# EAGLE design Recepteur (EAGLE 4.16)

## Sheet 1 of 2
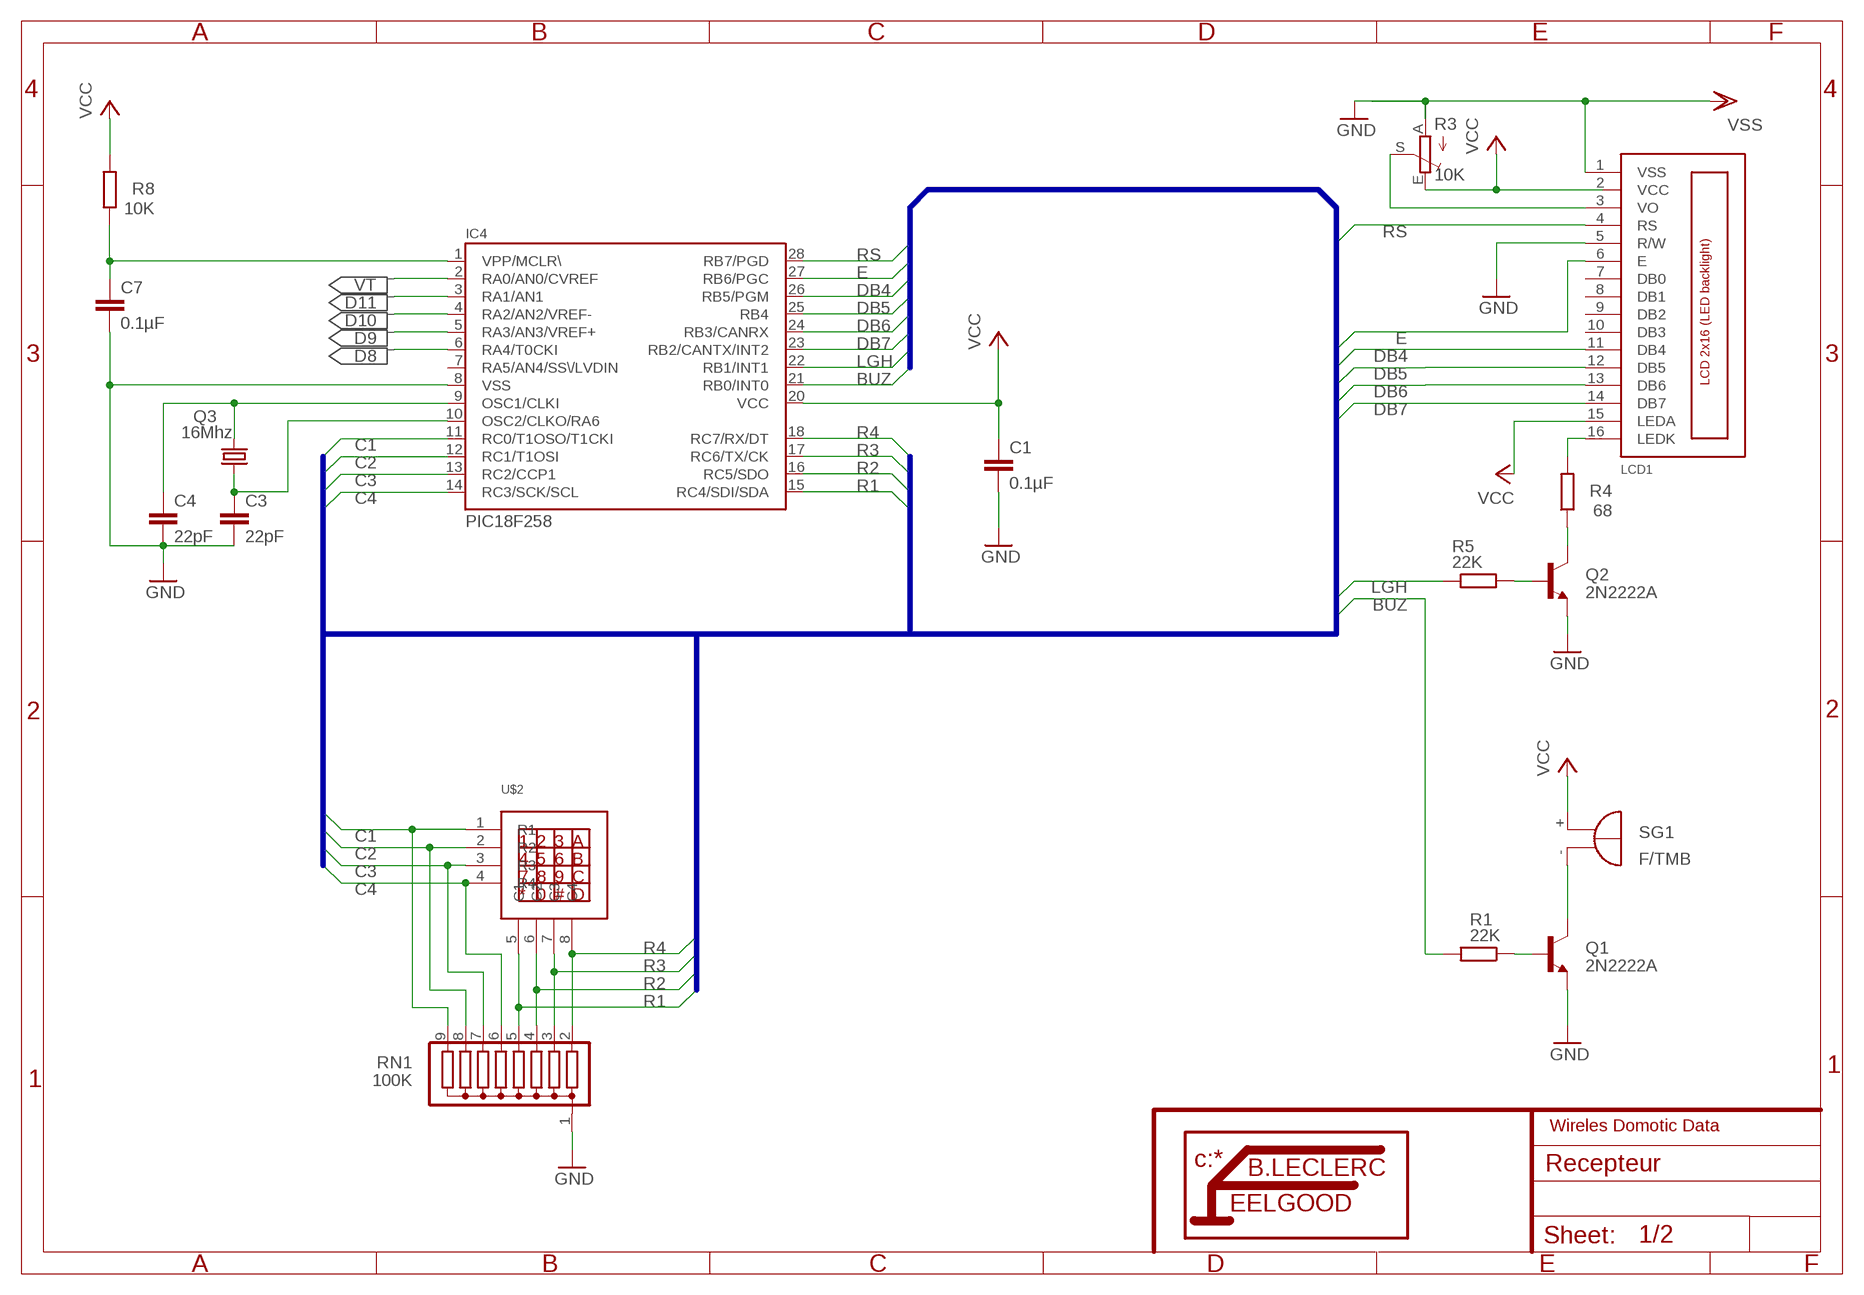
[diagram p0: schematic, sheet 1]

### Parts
C1  0.1µF  C-EU102-043X133  [C102-043X133]
C3  22pF  C-EU025-030X050  [C025-030X050]
C4  22pF  C-EU025-030X050  [C025-030X050]
C7  0.1µF  C-EU102-043X133  [C102-043X133]
IC4  PIC18F258  [DIL28]
LCD1  LCD_2X16_SIL  [HY-1602F]
Q1  2N2222A  [TO18]
Q2  2N2222A  [TO18]
Q3  16Mhz  CRYTALHC49U70  [HC49U70]
R1  22K  R-EU_0207/10  [0207/10]
R3  10K  TRIM_EU-LI10  [LI10]
R4  68  R-EU_0207/10  [0207/10]
R5  22K  R-EU_0207/10  [0207/10]
R8  10K  R-EU_0207/10  [0207/10]
RN1  100K  G08R  [SIL9]
SG1  F/TMB  [F/TMB]
U$2  KEYPAD4X4  [KEYPAD4X4]

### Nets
BUZ: IC4.21(RB0/INT0) R1.2
C1: IC4.11(RC0/T1OSO/T1CKI) RN1.9 U$2.1(R1)
C2: IC4.12(RC1/T1OSI) RN1.8 U$2.2(R2)
C3: IC4.13(RC2/CCP1) RN1.7 U$2.3(R3)
C4: IC4.14(RC3/SCK/SCL) RN1.6 U$2.4(R4)
D8: IC4.6(RA4/T0CKI) ; also sheet 2
D9: IC4.5(RA3/AN3/VREF+) ; also sheet 2
D10: IC4.4(RA2/AN2/VREF-) ; also sheet 2
D11: IC4.3(RA1/AN1) ; also sheet 2
DB4: IC4.26(RB5/PGM) LCD1.11(DB4)
DB5: IC4.25(RB4) LCD1.12(DB5)
DB6: IC4.24(RB3/CANRX) LCD1.13(DB6)
DB7: IC4.23(RB2/CANTX/INT2) LCD1.14(DB7)
E: IC4.27(RB6/PGC) LCD1.6(E)
GND: C1.2 C3.2 C4.2 C7.2 IC4.8(VSS) LCD1.1(VSS) LCD1.5(R/W) Q1.1(E) Q2.1(E) R3.A RN1.1 ; supply symbol labelled VSS ; also sheet 2
LGH: IC4.22(RB1/INT1) R5.1
N$1: LCD1.3(VO) R3.S
N$2: LCD1.16(LEDK) R4.2
N$3: Q2.3(C) R4.1
N$4: C7.1 IC4.1(VPP/MCLR\) R8.1
N$5: Q2.2(B) R5.2
N$6: C3.1 IC4.10(OSC2/CLKO/RA6) Q3.1
N$9: C4.1 IC4.9(OSC1/CLKI) Q3.2
N$12: Q1.3(C) SG1.-
N$13: Q1.2(B) R1.1
R1: IC4.15(RC4/SDI/SDA) RN1.5 U$2.5(C1)
R2: IC4.16(RC5/SDO) RN1.4 U$2.6(C2)
R3: IC4.17(RC6/TX/CK) RN1.3 U$2.7(C3)
R4: IC4.18(RC7/RX/DT) RN1.2 U$2.8(C4)
RS: IC4.28(RB7/PGD) LCD1.4(RS)
VCC: C1.1 IC4.20(VCC) LCD1.15(LEDA) R3.E R8.2 SG1.+ ; also sheet 2
VT: IC4.2(RA0/AN0/CVREF) ; also sheet 2
Unconnected: IC4.7(RA5/AN4/SS\/LVDIN) LCD1.7(DB0) LCD1.8(DB1) LCD1.9(DB2) LCD1.10(DB3)

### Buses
B$2

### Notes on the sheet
- Wireles Domotic Data

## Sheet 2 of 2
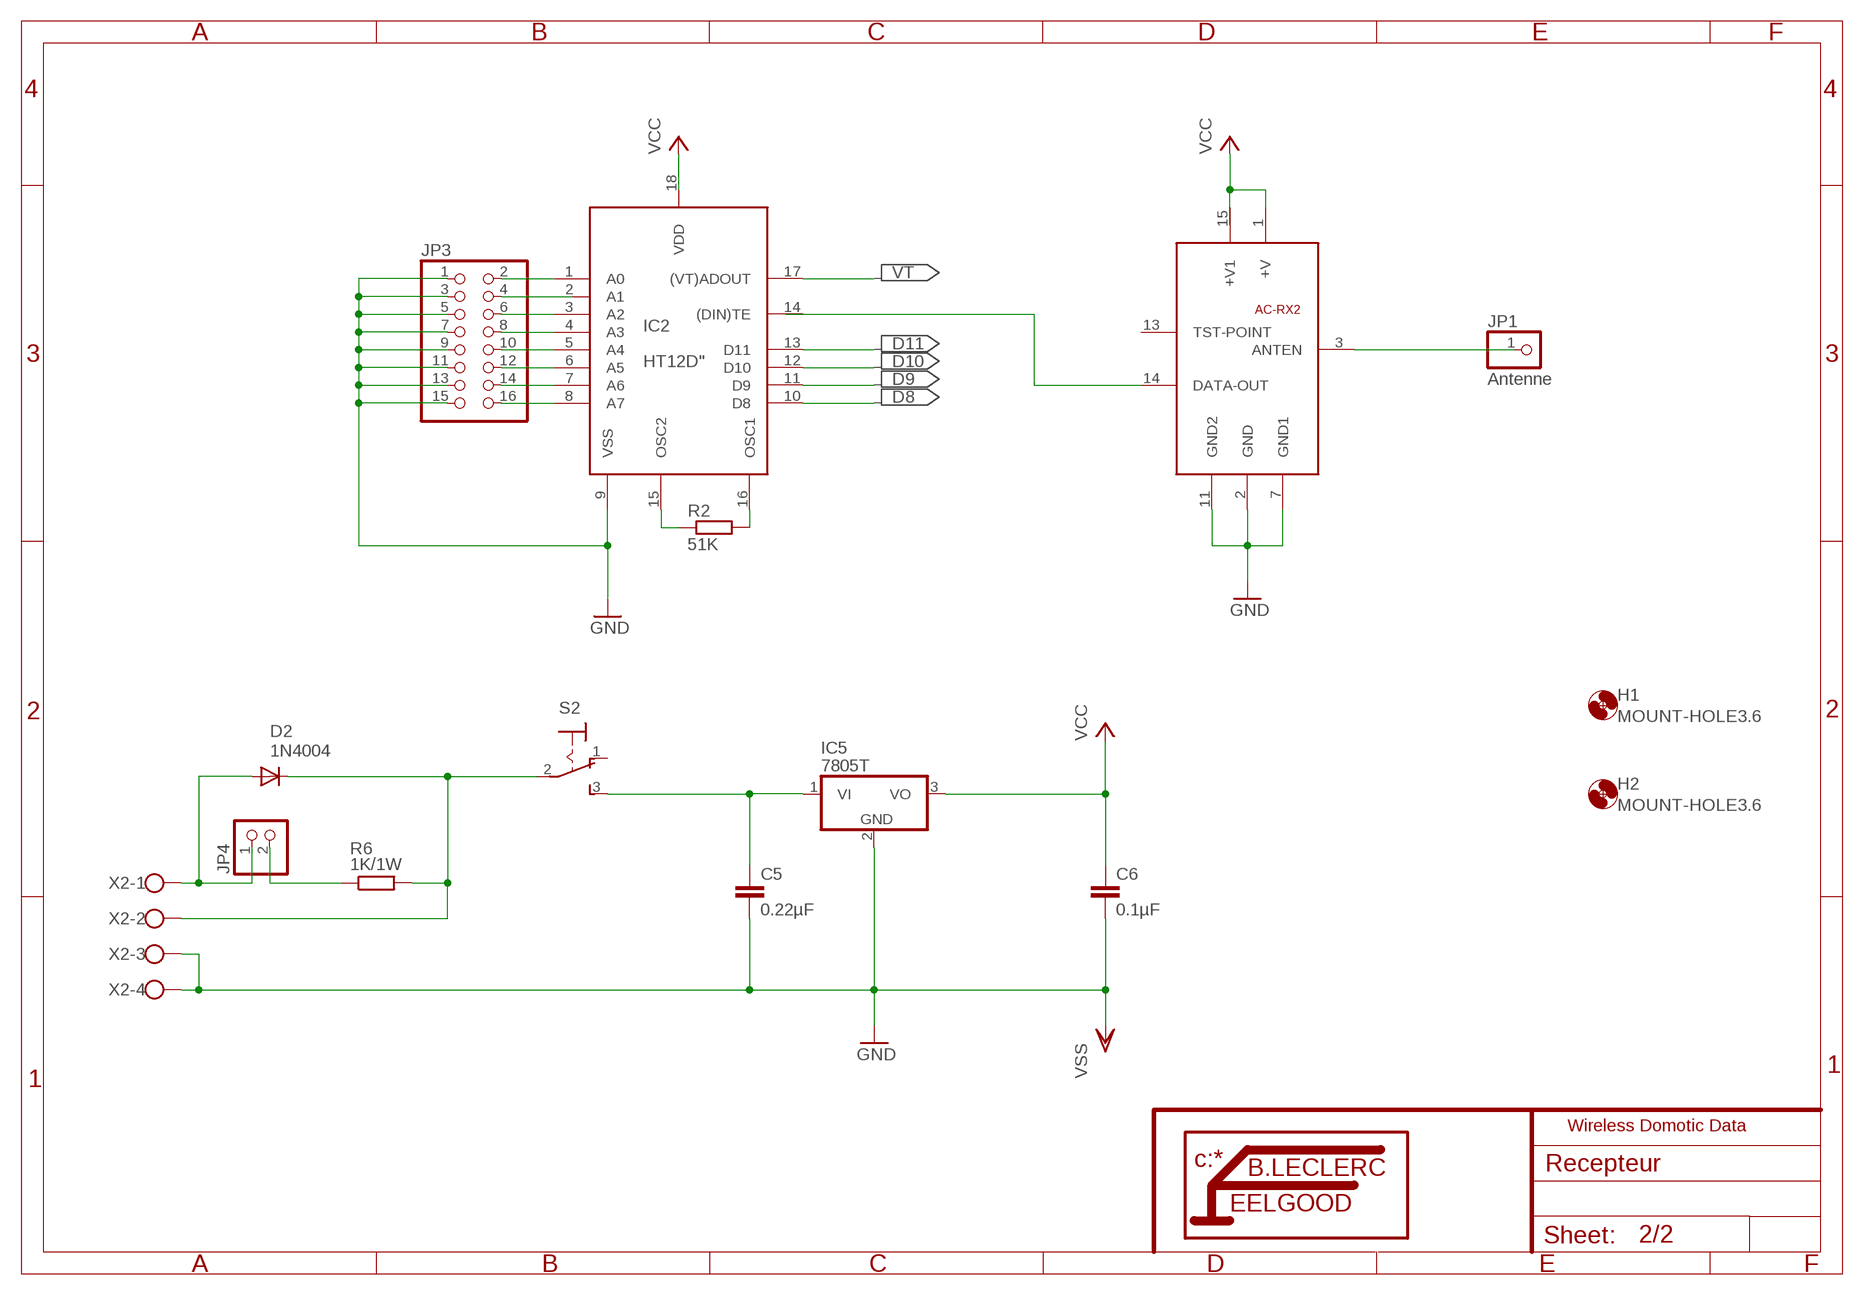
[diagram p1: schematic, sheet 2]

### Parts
AC-RX2  AUREL_AC-RX2  [AUREL_AC-RX2]
C5  0.22µF  C-EU102-043X133  [C102-043X133]
C6  0.1µF  C-EU102-043X133  [C102-043X133]
D2  1N4004  [DO41-10]
H1  MOUNT-HOLE3.6  [3,6]
H2  MOUNT-HOLE3.6  [3,6]
IC2  HT12D"  [18-DIP-A]
IC5  7805T  [TO220H]
JP1  Antenne  PINHD-1X1  [1X01]
JP3  PINHD-2X8  [2X08]
JP4  PINHD-1X2  [1X02]
R2  51K  R-EU_0207/10  [0207/10]
R6  1K/1W  R-EU_0207/10  [0207/10]
S2  320-916  [320-916]
X2  W237-4  [W237-4]

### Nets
D8: IC2.10(D8) ; also sheet 1
D9: IC2.11(D9) ; also sheet 1
D10: IC2.12(D10) ; also sheet 1
D11: IC2.13(D11) ; also sheet 1
GND: AC-RX2.2(GND) AC-RX2.7(GND1) AC-RX2.11(GND2) C5.2 C6.2 IC2.9(VSS) IC5.2(GND) JP3.1 JP3.3 JP3.5 JP3.7 JP3.9 JP3.11 JP3.13 JP3.15 X2.3 X2.4 ; supply symbol labelled VSS ; also sheet 1
N$11: IC2.1(A0) JP3.2
N$14: IC2.2(A1) JP3.4
N$15: IC2.3(A2) JP3.6
N$16: IC2.4(A3) JP3.8
N$17: IC2.5(A4) JP3.10
N$18: IC2.6(A5) JP3.12
N$19: IC2.7(A6) JP3.14
N$20: IC2.8(A7) JP3.16
N$21: AC-RX2.14(DATA-OUT) IC2.14((DIN)TE)
N$22: IC2.15(OSC2) R2.1
N$23: IC2.16(OSC1) R2.2
N$24: C5.1 IC5.1(VI) S2.3(S)
N$25: AC-RX2.3(ANTEN) JP1.1
N$26: D2.A JP4.1 X2.1
N$27: JP4.2 R6.1
N$28: D2.C R6.2 S2.2(P) X2.2
VCC: AC-RX2.1(+V) AC-RX2.15(+V1) C6.1 IC2.18(VDD) IC5.3(VO) ; also sheet 1
VT: IC2.17((VT)ADOUT) ; also sheet 1
Unconnected: AC-RX2.13(TST-POINT) S2.1(O)

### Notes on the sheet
- Wireless Domotic Data

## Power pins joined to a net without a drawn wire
VCC: LCD1.2(VCC)

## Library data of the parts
AC-RX2 = aurel:AUREL_AC-RX2
C1 C3-C7 = rcl:C-EU: CAPACITOR, European symbol
D2 = diode:1N4004: DIODE
H1 H2 = holes:MOUNT-HOLE: MOUNTING HOLE with drill center marker
IC2 = holtek:HT12D: decoder = receiver ic
IC4 = microchip-18f258:PIC18F258
IC5 = linear:78*: Positive VOLTAGE REGULATOR Source: http://cache.national.com/ds/LM/LM78L05.pdf http://www.fairchildsemi.com/ds/LM/LM7805.pdf
JP1 = pinhead:PINHD-1X1: PIN HEADER
JP3 = pinhead:PINHD-2X8: PIN HEADER
JP4 = pinhead:PINHD-1X2: PIN HEADER
LCD1 = lcd_2x16_led_backlight:LCD_2X16_SIL
Q1 Q2 = transistor-npn:2N2222*: NPN Transistor
Q3 = crystal:CRYTAL: CRYSTAL
R1 R2 R4-R6 R8 = rcl:R-EU_: RESISTOR, European symbol
R3 = pot:TRIM_EU-: POTENTIOMETER
RN1 = resistor-sil:G08R: SIL RESISTOR
S2 = switch:320-916: TOGGLE SWITCH distributor RS Components
SG1 = buzzer:F/TMB: BUZZER
U$2 = keypad4x4_ece:KEYPAD4X4
X2 = con-wago-500:W237-4: WAGO SCREW CLAMP

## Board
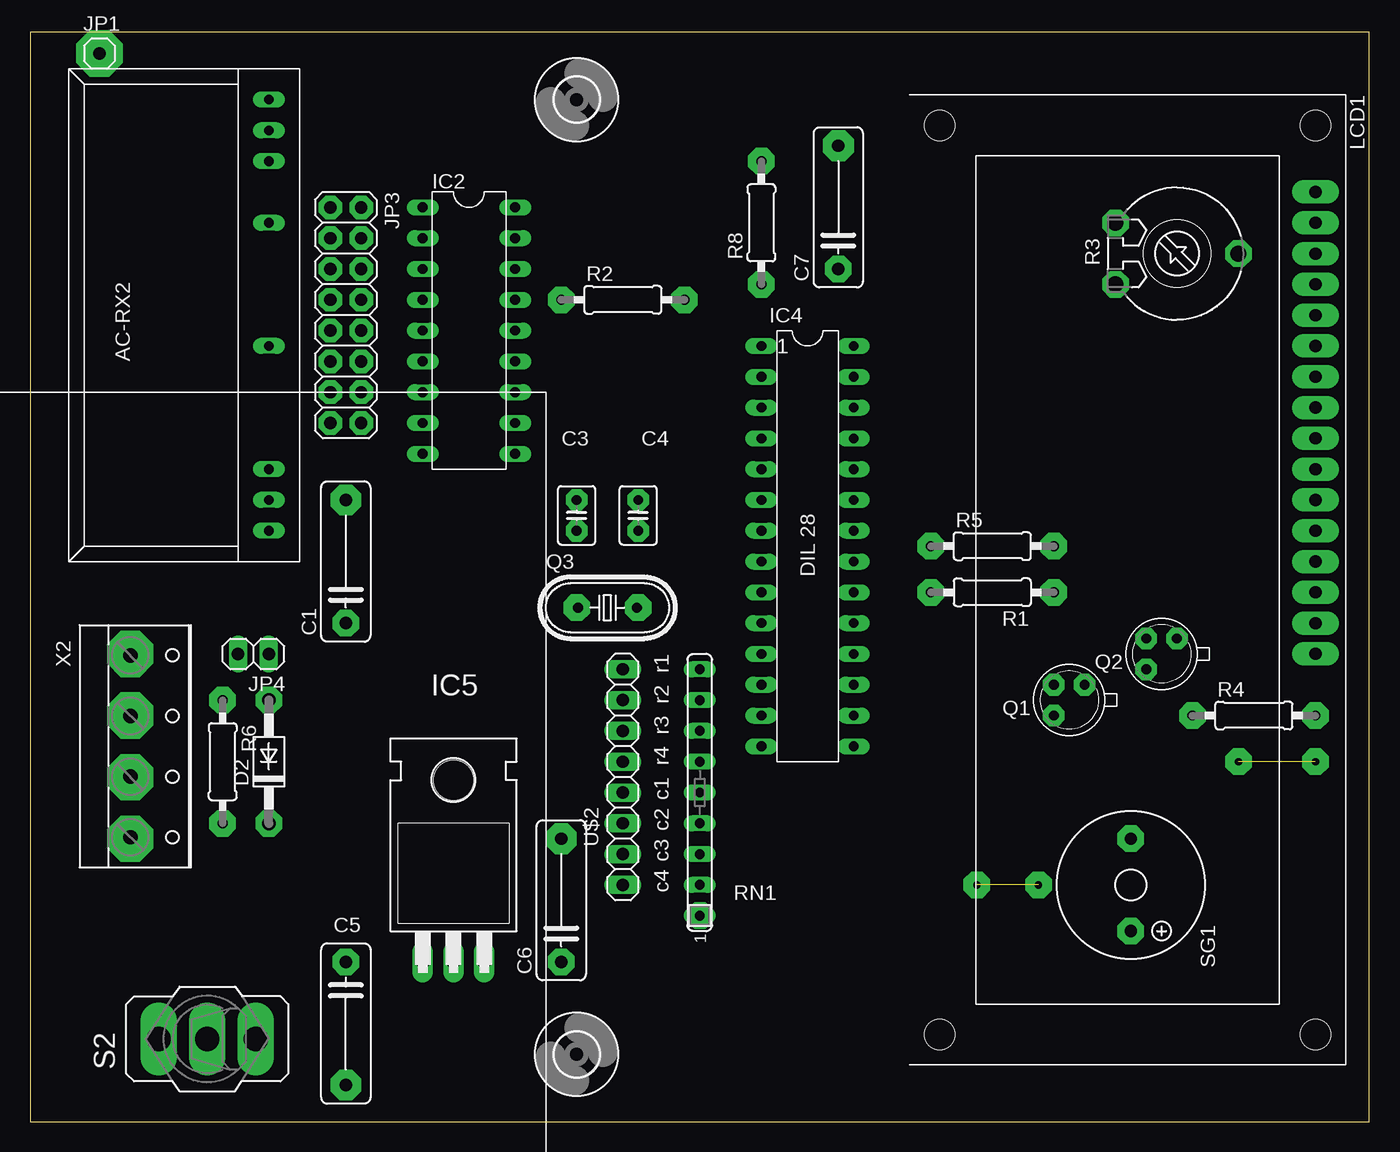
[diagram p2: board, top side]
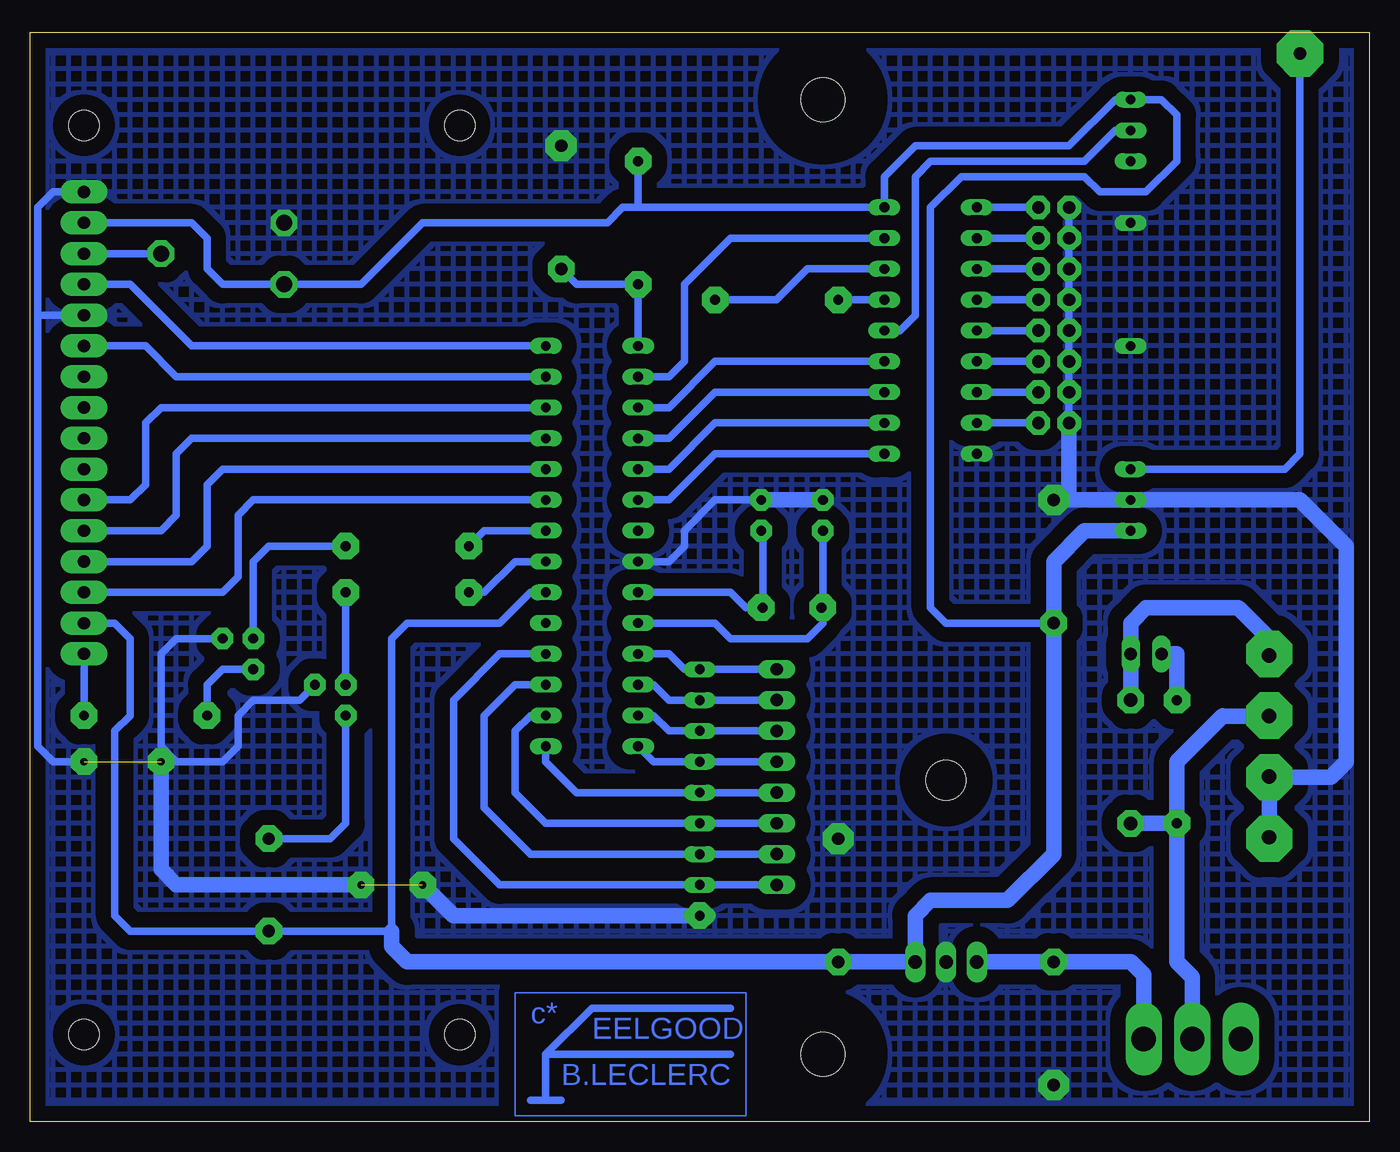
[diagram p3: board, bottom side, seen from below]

Size 110.47 x 89.84 mm. Coordinates in mm from the lower left corner, seen from the top.
Outline: 0,0 110.47,0 110.47,89.84 0,89.84 0,0
Copper layers (1*16): Top 0.035mm / dielectric 1.5mm / Bottom 0.035mm
Design rules "default": minimum track width 10mil, minimum drill 24mil, track to track 8mil, track to pad 8mil, pad to pad 8mil, via to via 8mil, smd to smd 8mil, copper to edge 40mil, drill to drill 8mil, minimum pad ring 10mil, minimum via ring 8mil, stop-mask expansion 4mil, vias tented up to drill 0mil, thermal gap 10mil

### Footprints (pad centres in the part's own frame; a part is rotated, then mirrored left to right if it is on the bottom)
AUREL_AC-RX2 = drill 0.8 long: 1 -17.78,-7.62; 2 -15.24,-7.62; 3 -12.7,-7.62; 7 -2.54,-7.62; 11 7.62,-7.62; 13 12.7,-7.62; 14 15.24,-7.62; 15 17.78,-7.62
C102-043X133 = drill 1.016 octagon: 1 -5.08,0; 2 5.08,0
C025-030X050 = drill 0.813 octagon: 1 -1.27,0; 2 1.27,0
DO41-10 = drill 1.118 round: A 5.08,0; C -5.08,0
3,6 = hole 3.6: 0,0
18-DIP-A = drill 0.813 long: 1 -10.16,-3.81; 2 -7.62,-3.81; 3 -5.08,-3.81; 4 -2.54,-3.81; 5 0,-3.81; 6 2.54,-3.81; 7 5.08,-3.81; 8 7.62,-3.81; 9 10.16,-3.81; 10 10.16,3.81; 11 7.62,3.81; 12 5.08,3.81; 13 2.54,3.81; 14 0,3.81; 15 -2.54,3.81; 16 -5.08,3.81; 17 -7.62,3.81; 18 -10.16,3.81
DIL28 = drill 0.8 long: 1 -3.81,16.51; 2 -3.81,13.97; 3 -3.81,11.43; 4 -3.81,8.89; 5 -3.81,6.35; 6 -3.81,3.81; 7 -3.81,1.27; 8 -3.81,-1.27; 9 -3.81,-3.81; 10 -3.81,-6.35; 11 -3.81,-8.89; 12 -3.81,-11.43; 13 -3.81,-13.97; 14 -3.81,-16.51; 15 3.81,-16.51; 16 3.81,-13.97; 17 3.81,-11.43; 18 3.81,-8.89; 19 3.81,-6.35; 20 3.81,-3.81; 21 3.81,-1.27; 22 3.81,1.27; 23 3.81,3.81; 24 3.81,6.35; 25 3.81,8.89; 26 3.81,11.43; 27 3.81,13.97; 28 3.81,16.51
TO220H = drill 1.118 long: 1 -2.54,-10.16; 2 0,-10.16; 3 2.54,-10.16 | hole 3.302: 0,4.826
1X01 = drill 1.016 octagon: 1 0,0
2X08 = drill 1.016 octagon: 1 -8.89,-1.27; 2 -8.89,1.27; 3 -6.35,-1.27; 4 -6.35,1.27; 5 -3.81,-1.27; 6 -3.81,1.27; 7 -1.27,-1.27; 8 -1.27,1.27; 9 1.27,-1.27; 10 1.27,1.27; 11 3.81,-1.27; 12 3.81,1.27; 13 6.35,-1.27; 14 6.35,1.27; 15 8.89,-1.27; 16 8.89,1.27
1X02 = drill 1.016 long: 1 -1.27,0; 2 1.27,0
HY-1602F = drill 1 pad 1.93 long: 1 2.54,0; 2 5.08,0; 3 7.62,0; 4 10.16,0; 5 12.7,0; 6 15.24,0; 7 17.78,0; 8 20.32,0; 9 22.86,0; 10 25.4,0; 11 27.94,0; 12 30.48,0; 13 33.02,0; 14 35.56,0; 15 38.1,0; 16 40.64,0 | hole 2.5: -2.96,0; 72.04,0; -2.96,-31; 72.04,-31
TO18 = drill 0.813 octagon: 1 -1.27,-1.27; 2 1.27,-1.27; 3 1.27,1.27
HC49U70 = drill 0.813 round: 1 -2.413,0; 2 2.413,0
0207/10 = drill 0.813 octagon: 1 -5.08,0; 2 5.08,0
LI10 = drill 1.321 octagon: A -2.54,-5.08; E 2.54,-5.08; S 0,5.08
SIL9 = drill 0.813 long: 1 -10.16,0; 2 -7.62,0; 3 -5.08,0; 4 -2.54,0; 5 0,0; 6 2.54,0; 7 5.08,0; 8 7.62,0; 9 10.16,0
320-916 = drill 2.007 long: 1 0,4.013; 2 0,0; 3 0,-4.013
F/TMB = drill 1.016 pad 2.159 octagon: + 3.81,0; - -3.81,0
KEYPAD4X4 = drill 1.016 long: 1 -13.97,1.27; 2 -11.43,1.27; 3 -8.89,1.27; 4 -6.35,1.27; 5 -3.81,1.27; 6 -1.27,1.27; 7 1.27,1.27; 8 3.81,1.27
W237-4 = drill 1.194 long: 1 -7.5,-1.27; 2 -2.5,-1.27; 3 2.5,-1.27; 4 7.5,-1.27

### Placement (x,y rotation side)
AC-RX2  12.06,66.51 90 top
C1  26.03,46.19 90 top
C3  45.08,50 90 top
C4  50.16,50 90 top
C5  26.03,8.09 270 top
C6  43.81,18.25 90 top
C7  66.67,75.4 90 top
D2  19.68,29.68 90 top
H1  45.08,5.55 0 top
H2  45.08,84.29 0 top
IC2  36.19,65.24 270 top
IC4  64.13,47.46 0 top
IC5  34.92,23.33 0 top
JP1  5.71,88.1 0 top
JP3  26.03,66.51 270 top
JP4  18.41,38.57 180 top
LCD1  106.04,79.21 270 top
Q1  85.72,34.76 180 top
Q2  93.34,38.57 180 top
Q3  47.62,42.38 0 top
R1  79.37,43.65 180 top
R2  48.89,67.78 0 top
R3  94.61,71.59 270 top
R4  100.96,33.49 0 top
R5  79.37,47.46 0 top
R6  15.87,29.68 270 top
R8  60.32,74.13 90 top
RN1  55.24,27.14 90 top
S2  14.6,6.82 90 top
SG1  90.8,19.52 270 top
U$2  47.62,23.33 270 top
U$4  [LITTFEEL]  67.94,-2.07 0 bottom
X2  9.52,30.95 270 top

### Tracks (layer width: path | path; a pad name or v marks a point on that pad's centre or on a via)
BUZ
  Bottom 0.61: IC4.21 70.48,46.19 73.02,43.65 R1.2
C1
  Bottom 0.61: U$2.1 RN1.9 56.51,37.3 57.78,38.57 IC4.11
C2
  Bottom 0.61: U$2.2 RN1.8 57.78,34.76 59.05,36.03 IC4.12
C3
  Bottom 0.61: U$2.3 RN1.7 57.78,32.22 59.05,33.49 IC4.13
C4
  Bottom 0.61: U$2.4 RN1.6 59.05,29.68 IC4.14
D8
  Bottom 0.61: IC2.10 53.97,55.08 57.78,51.27 IC4.6
D9
  Bottom 0.61: IC2.11 53.97,57.62 57.78,53.81 IC4.5
D10
  Bottom 0.61: IC2.12 53.97,60.16 57.78,56.35 IC4.4
D11
  Bottom 0.61: IC2.13 53.97,62.7 57.78,58.89 IC4.3
DB4
  Bottom 0.61: IC4.26 99.69,58.89 100.96,57.62 100.96,52.54 102.23,51.27 LCD1.11
DB5
  Bottom 0.61: IC4.25 97.15,56.35 98.42,55.08 98.42,50 99.69,48.73 LCD1.12
DB6
  Bottom 0.61: IC4.24 94.61,53.81 95.88,52.54 95.88,47.46 97.15,46.19 LCD1.13
DB7
  Bottom 0.61: IC4.23 92.07,51.27 93.34,50 93.34,44.92 94.61,43.65 LCD1.14
E
  Bottom 0.61: IC4.27 98.42,61.43 100.96,63.97 LCD1.6
GND  (via drill 0.6 pad 1.78, 0.6 pad 1.93, 0.6 pad 2.18, 0.6 pad 2.54)  (2 unrouted)
  Bottom 0.61: LCD1.1 108.58,76.67 109.85,75.4 109.85,66.51 | 109.85,66.51 LCD1.5 | Q2.1 98.42,39.84 99.69,38.57 99.69,30.95 98.42,29.68 94.61,29.68 93.34,30.95 93.34,33.49 92.07,34.76 88.26,34.76 Q1.1 | C3.2 C4.2 53.97,51.27 56.51,48.73 56.51,47.46 57.78,46.19 IC4.8 | 109.85,66.51 109.85,30.95 108.58,29.68 v106.04,29.68 | JP3.1 JP3.3 JP3.5 JP3.7 JP3.9 JP3.11 JP3.13 JP3.15
  Bottom 1.27: JP3.15 24.76,51.27 AC-RX2.2 5.71,51.27 1.9,47.46 1.9,29.68 3.17,28.41 8.25,28.41 X2.3 X2.4 8.25,23.33 | RN1.1 75.56,16.98 v78.1,19.52 | v99.69,29.68 99.69,20.79 98.42,19.52 v83.18,19.52 | C3.2 C4.2
  other vias: 89.53,74.13 50.16,51.27 45.08,51.27 55.24,16.98 24.76,75.4 24.76,72.86 24.76,70.32 24.76,67.78 24.76,65.24 24.76,62.7 24.76,60.16 24.76,57.62 66.67,80.48 26.03,51.27 26.03,3.01 43.81,23.33
  pour Bottom (isolate 1.27, no thermals, hatched): 0.63,89.37 109.85,89.37 109.85,0.47 0.63,0.47
LGH
  Bottom 0.61: IC4.22 73.02,48.73 R5.1
N$1
  Bottom 0.61: R3.S LCD1.3
N$2
  Bottom 0.61: R4.2 LCD1.16
N$3
  Bottom 0.61: Q2.3 94.61,37.3 95.88,36.03 R4.1
N$4
  Bottom 0.61: IC4.1 R8.1 65.4,69.05 C7.1
N$5
  Bottom 0.61: R5.2 90.8,47.46 92.07,46.19 Q2.2
N$6
  Bottom 0.61: 45.21,48.6 C3.1 45.08,42.38 | IC4.10 53.97,41.11 52.7,39.84 46.35,39.84 45.08,41.11 45.08,42.38 | Q3.1 45.08,42.38
N$7  (via drill 0.6 pad 2.18)
  other vias: 60.32,79.21
N$8  (via drill 0.6 pad 2.18)
  other vias: 60.32,69.05
N$9
  Bottom 0.61: C4.1 50.03,48.6 50.03,42.51 50.16,42.38 | IC4.9 52.7,43.65 51.43,42.38 50.16,42.38 | Q3.2 50.16,42.38
N$11
  Bottom 0.61: JP3.2 IC2.1
N$12
  Bottom 0.61: Q1.3 84.45,24.6 85.72,23.33 SG1.-
N$13
  Bottom 0.61: Q1.2 R1.1
N$14
  Bottom 0.61: JP3.4 IC2.2
N$15
  Bottom 0.61: JP3.6 IC2.3
N$16
  Bottom 0.61: JP3.8 IC2.4
N$17
  Bottom 0.61: JP3.10 IC2.5
N$18
  Bottom 0.61: JP3.12 IC2.6
N$19
  Bottom 0.61: JP3.14 IC2.7
N$20
  Bottom 0.61: JP3.16 IC2.8
N$21
  Bottom 0.61: IC2.14 38.73,65.24 37.46,66.51 37.46,77.94 36.19,79.21 23.49,79.21 20.95,81.75 AC-RX2.14
N$22
  Bottom 0.61: IC2.15 R2.1
N$23
  Bottom 0.61: IC2.16 46.35,70.32 48.89,67.78 R2.2
N$24
  Bottom 1.27: S2.3 18.61,12.1 19.68,13.17 C5.1 IC5.1
N$25
  Bottom 0.61: AC-RX2.3 6.98,53.81 5.71,55.08 JP1.1
N$26
  Bottom 1.27: X2.1 8.25,39.84 10.79,42.38 18.41,42.38 19.68,41.11 JP4.1 D2.A
N$27
  Bottom 1.27: JP4.2 15.87,38.57 R6.1
N$28
  Bottom 1.27: X2.2 12.02,33.45 12.06,33.49 15.87,29.68 R6.2 | R6.2 D2.C | R6.2 15.87,13.17 14.6,11.9 S2.2
N$29  (via drill 0.6 pad 1.93)
  other vias: 27.3,67.78
N$30  (via drill 0.6 pad 2.18)
  other vias: 66.67,70.32
N$31  (via drill 0.6 pad 1.93)
  other vias: 27.3,65.24
N$32  (via drill 0.6 pad 2.18)
  other vias: 99.69,71.59
N$33  (via drill 0.6 pad 2.18)
  other vias: 89.53,69.05
N$34  (via drill 0.6 pad 2.18)
  other vias: 43.81,67.78
N$35  (via drill 0.6 pad 2.18)
  other vias: 53.97,67.78
N$36  (via drill 0.6 pad 1.93)
  other vias: 27.3,57.62
N$39  (via drill 0.6 pad 1.93)
  other vias: 27.3,70.32
N$40  (via drill 0.6 pad 1.93)
  other vias: 27.3,72.86
N$41  (via drill 0.6 pad 1.93)
  other vias: 27.3,75.4
N$42  (via drill 0.6 pad 2.18)
  other vias: 26.03,41.11
N$44  (via drill 0.6 pad 2.18)
  other vias: 45.08,42.38
N$45  (via drill 0.6 pad 2.18)
  other vias: 50.16,42.38
N$46  (via drill 0.6 pad 2.18)
  other vias: 74.29,47.46
N$47  (via drill 0.6 pad 2.18)
  other vias: 84.45,47.46
N$48  (via drill 0.6 pad 2.18)
  other vias: 84.45,43.65
N$49  (via drill 0.6 pad 2.18)
  other vias: 43.81,13.17
N$50  (via drill 0.6 pad 1.93)
  other vias: 27.3,62.7
N$51  (via drill 0.6 pad 1.93)
  other vias: 27.3,60.16
N$52  (via drill 0.6 pad 2.18)
  other vias: 19.68,24.6
N$53  (via drill 0.6 pad 2.18)
  other vias: 19.68,34.76
N$57  (via drill 0.6 pad 2.18)
  other vias: 90.8,23.33
N$58  (via drill 0.6 pad 2.18)
  other vias: 106.04,33.49
N$59  (via drill 0.6 pad 2.18)
  other vias: 95.88,33.49
N$60  (via drill 0.6 pad 2.18)
  other vias: 26.03,13.17
N$61  (via drill 0.6 pad 2.18)
  other vias: 15.87,34.76
N$62  (via drill 0.6 pad 2.18)
  other vias: 15.87,24.6
N$67  (via drill 0.6 pad 2.18)
  other vias: 90.8,15.71
N$68  (via drill 0.6 pad 2.18)
  other vias: 74.29,43.65
N$69  (via drill 0.6 pad 1.78)
  other vias: 86.99,36.03
N$70  (via drill 0.6 pad 1.78)
  other vias: 92.07,37.3
N$71  (via drill 0.6 pad 1.78)
  other vias: 92.07,39.84
N$72  (via drill 0.6 pad 1.78)
  other vias: 94.61,39.84
N$73  (via drill 0.6 pad 1.78)
  other vias: 84.45,33.49
N$74  (via drill 0.6 pad 1.78)
  other vias: 84.45,36.03
N$77  (via drill 0.6 pad 1.78)
  other vias: 50.16,48.73
N$78  (via drill 0.6 pad 1.78)
  other vias: 45.08,48.73
N$79  (via drill 0.6 pad 3.81)
  other vias: 8.25,33.49
N$80  (via drill 0.6 pad 3.81)
  other vias: 8.25,28.41
N$81  (via drill 0.6 pad 3.81)
  other vias: 8.25,23.33
N$82  (via drill 0.6 pad 3.81)
  other vias: 8.25,38.57
N$83  (via drill 0.6 pad 3.81)
  other vias: 5.71,88.1
R1
  Bottom 0.61: U$2.5 RN1.5 65.4,27.14 67.94,29.68 IC4.15
R2
  Bottom 0.61: IC4.16 69.21,33.49 70.48,32.22 70.48,27.14 67.94,24.6 RN1.4 U$2.6
R3
  Bottom 0.61: IC4.17 70.48,36.03 73.02,33.49 73.02,25.87 69.21,22.06 RN1.3 U$2.7
R4
  Bottom 0.61: IC4.18 71.75,38.57 75.56,34.76 75.56,23.33 71.75,19.52 RN1.2 U$2.8
RS
  Bottom 0.61: IC4.28 97.15,63.97 102.23,69.05 LCD1.4
VCC
  Bottom 0.61: 60.32,75.4 IC2.18 40,77.94 37.46,80.48 24.76,80.48 20.95,84.29 AC-RX2.15 17.14,84.29 15.87,83.02 15.87,79.21 18.41,76.67 22.22,76.67 23.49,77.94 33.65,77.94 36.19,75.4 36.19,42.38 34.92,41.11 C1.1 | LCD1.2 97.15,74.13 95.88,72.86 95.88,70.32 94.61,69.05 R3.E 83.18,69.05 78.1,74.13 62.86,74.13 61.59,75.4 60.32,75.4 | 60.32,75.4 R8.2 | LCD1.15 103.5,41.11 102.23,39.84 102.23,33.49 103.5,32.22 103.5,16.98 102.23,15.71 SG1.+ 80.64,15.71 80.64,39.84 79.37,41.11 71.75,41.11 69.21,43.65 IC4.20 | IC5.3 C6.1
  Bottom 1.27: AC-RX2.1 23.49,48.73 26.03,46.19 C1.1 26.03,22.06 29.84,18.25 36.19,18.25 37.46,16.98 IC5.3 C6.1 79.37,13.17 80.64,14.44 80.64,15.71
VT
  Bottom 0.61: IC2.17 52.7,72.86 56.51,69.05 56.51,62.7 57.78,61.43 IC4.2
